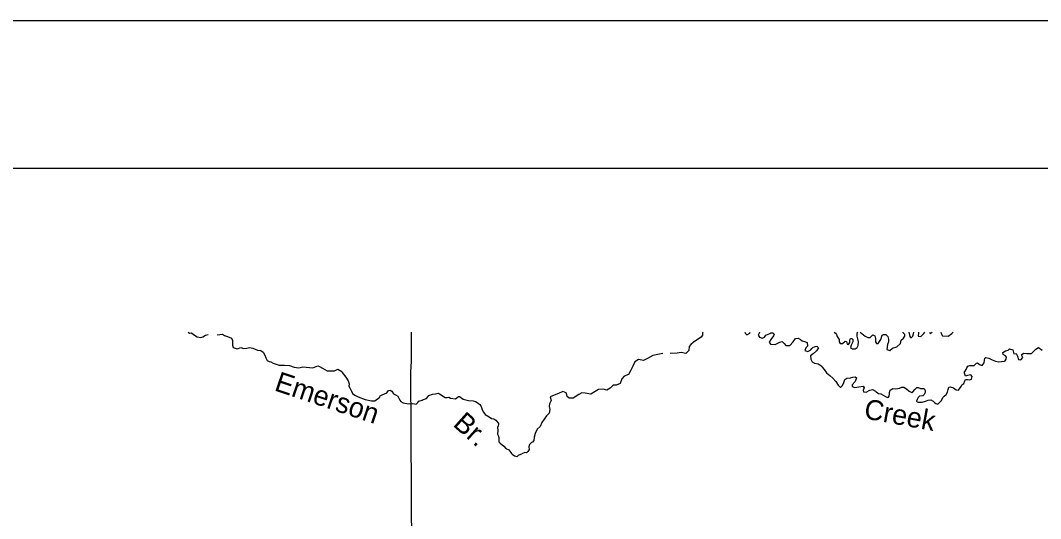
# Model space of a CAD drawing. Extents: x -492261 to -432772, y 1441225 to 1452922.
# Drawn here: x -459563.1 to -459293.9, y 1452515.2 to 1452646.6 of the extents above; entities that cross this region are included whole.
import ezdxf

# ---------------------------------------------------------------- set-up
doc = ezdxf.new("R2010")
doc.units = 0
for name, color, linetype in [('Default', 7, 'Continuous'), ('R_Border', 7, 'Continuous'), ('R_No Plot', 7, 'Continuous')]:
    doc.layers.add(name, color=color, linetype=linetype)

msp = doc.modelspace()

# ---------------------------------------------------------------- linework, layer by layer
at = {"layer": 'Default'}
for points in [[(-459518.78, 1452564.34), (-459518.45, 1452564.12), (-459517.9, 1452564.16), (-459517.4, 1452563.78), (-459516.45, 1452563.09), (-459515.5, 1452562.97), (-459514.93, 1452563.14), (-459514.23, 1452563.58), (-459513.49, 1452563.74)], [(-459511.17, 1452563.64), (-459509.74, 1452563.8), (-459509.24, 1452563.51), (-459508.43, 1452563.18), (-459507.41, 1452562.74), (-459507.1, 1452562.17), (-459507.12, 1452560.89), (-459506.93, 1452560.32), (-459505.92, 1452559.94), (-459504.93, 1452560.27), (-459504.18, 1452560.09), (-459503.33, 1452560.12), (-459502.59, 1452560.35), (-459501.78, 1452560.13), (-459500.5, 1452559.64), (-459499.62, 1452559.49), (-459499, 1452559.05), (-459498.58, 1452558.28), (-459498.29, 1452557.59), (-459497.94, 1452556.85), (-459497.41, 1452556.61), (-459496.99, 1452556.53), (-459496.4, 1452556.17), (-459494.8, 1452555.69), (-459493.36, 1452555.68), (-459492.1, 1452555.58), (-459490.81, 1452555.09), (-459489.63, 1452554.93), (-459488.54, 1452555.21), (-459487.65, 1452555.11), (-459485.93, 1452554.95), (-459484.59, 1452555.44), (-459484.14, 1452555.32), (-459483.37, 1452554.86), (-459482.16, 1452554.17), (-459480.17, 1452554.16), (-459479.34, 1452554.59), (-459478.27, 1452553.98), (-459478.14, 1452553.68), (-459477.22, 1452552.48), (-459476.55, 1452551.56), (-459476.37, 1452550.76), (-459476.45, 1452550.11), (-459476.07, 1452549.53), (-459475.75, 1452548.83), (-459475.44, 1452548.21), (-459474.79, 1452547.7), (-459473.91, 1452547.29), (-459472.11, 1452546.56), (-459470.47, 1452546.21), (-459469.56, 1452546.28), (-459468.26, 1452547.2), (-459468.12, 1452547.57), (-459467.6, 1452547.85), (-459466.36, 1452548.39), (-459465.96, 1452548.94), (-459465.54, 1452549.07), (-459465.1, 1452548.8), (-459464.6, 1452548.08), (-459464.06, 1452547.8), (-459463.49, 1452547.47), (-459462.97, 1452546.4)], [(-459458.97, 1452182.95), (-459458.72, 1452223.82), (-459458.96, 1452227.22), (-459459.32, 1452292.75), (-459459.97, 1452355.7), (-459459.94, 1452358.73), (-459460.05, 1452422.59), (-459460.04, 1452425.55), (-459459.65, 1452486.97), (-459459.67, 1452490.05), (-459460.02, 1452553.88), (-459459.91, 1452556.59), (-459459.92, 1452564.34)], [(-459383.03, 1452564.34), (-459383.06, 1452564.19), (-459383.11, 1452563.57), (-459383.48, 1452563.01), (-459384.93, 1452562.06), (-459385.59, 1452561.6), (-459386.17, 1452561.08), (-459386.62, 1452560.59), (-459386.67, 1452559.56), (-459387.45, 1452558.74), (-459388.74, 1452558.96), (-459389.76, 1452558.81), (-459391.66, 1452558.77)], [(-459371.89, 1452564.34), (-459371.81, 1452564.12), (-459371.36, 1452563.66), (-459370.61, 1452564.13), (-459370.49, 1452564.34)], [(-459368.03, 1452564.34), (-459368.09, 1452564.24), (-459368.37, 1452563.58), (-459368.05, 1452563.06), (-459367.32, 1452562.73), (-459366.73, 1452563.07), (-459366.36, 1452563.55), (-459365.79, 1452563.83), (-459365.36, 1452563.99), (-459365.04, 1452564.17), (-459364.53, 1452564.19), (-459364.22, 1452563.8), (-459364.4, 1452563.39), (-459365.03, 1452562.44), (-459365.49, 1452561.71), (-459365.13, 1452561.16), (-459363.95, 1452561.06), (-459362.71, 1452561.75), (-459362.11, 1452561.9), (-459361.59, 1452561.37), (-459361.1, 1452560.85), (-459360.05, 1452560.82), (-459359.18, 1452561.82), (-459358.54, 1452562.71), (-459357.82, 1452562.81), (-459357.26, 1452562.4), (-459356.84, 1452562.06), (-459356.17, 1452561.92), (-459355.52, 1452561.64), (-459355.38, 1452560.65), (-459355.8, 1452560.19), (-459356.08, 1452559.52), (-459355.3, 1452559.24), (-459354.49, 1452559.69), (-459354.21, 1452560.04), (-459353.86, 1452560.38), (-459352.94, 1452560.67), (-459352.52, 1452560.19), (-459352.99, 1452559.46), (-459353.93, 1452558.68), (-459354.6, 1452558.1), (-459354.54, 1452557.22), (-459354.19, 1452556.57), (-459353.5, 1452556.2), (-459352.6, 1452556.04), (-459352.14, 1452555.78), (-459351.62, 1452555.42), (-459351.48, 1452555.11), (-459350.99, 1452554.49), (-459350.4, 1452553.67), (-459349.5, 1452552.96), (-459348.72, 1452552.24), (-459347.93, 1452551.32), (-459347.31, 1452550.35), (-459346.64, 1452549.74), (-459346.14, 1452550.3), (-459345.79, 1452551.05), (-459345.58, 1452551.83), (-459345.02, 1452552.23), (-459344.03, 1452552.29), (-459343.43, 1452552.52), (-459342.79, 1452552.58), (-459342.45, 1452552.29), (-459342.83, 1452551.36), (-459343.58, 1452550.48), (-459343.64, 1452550.06), (-459342.9, 1452549.75), (-459341.88, 1452549.93), (-459340.69, 1452550.08), (-459340.44, 1452549.7), (-459340.69, 1452549.03), (-459340.62, 1452548.61), (-459339.93, 1452548.52), (-459338.98, 1452549.07), (-459338.2, 1452549.24), (-459337.44, 1452548.8), (-459337.26, 1452548.63), (-459336.69, 1452548.2), (-459336.02, 1452548.13), (-459334.84, 1452547.37), (-459334.27, 1452547.1), (-459334.05, 1452547.18), (-459333.82, 1452547.48), (-459333.74, 1452548.09), (-459333.73, 1452548.48), (-459333.6, 1452549.05), (-459332.85, 1452549.5), (-459332.16, 1452549.44), (-459331.55, 1452549.46), (-459331.15, 1452549.6), (-459330.53, 1452549.81), (-459329.96, 1452549.81), (-459329.26, 1452549.43), (-459328.56, 1452548.78), (-459327.85, 1452548.43), (-459327.58, 1452548.62), (-459327.04, 1452549.27)], [(-459348.37, 1452564.34), (-459348.04, 1452564.13), (-459347.78, 1452563.77), (-459347.53, 1452563.22), (-459347.06, 1452562.44), (-459347.07, 1452562.24), (-459347.04, 1452561.84), (-459346.8, 1452561.36), (-459346.18, 1452561.38), (-459345.49, 1452561.99), (-459345.09, 1452561.93), (-459344.95, 1452561.17), (-459344.54, 1452561.14), (-459344.25, 1452561.65), (-459344.26, 1452562.34), (-459344.03, 1452562.66), (-459343.66, 1452562.67), (-459343.39, 1452562.41), (-459343.43, 1452561.83), (-459343.84, 1452560.93), (-459344, 1452560.31), (-459343.49, 1452560), (-459342.85, 1452559.98), (-459342.28, 1452560.31), (-459341.98, 1452560.87), (-459341.93, 1452561.81), (-459342.09, 1452562.59), (-459342.25, 1452563.27), (-459342.29, 1452564.17), (-459342.15, 1452564.34)], [(-459341.46, 1452564.34), (-459341.03, 1452563.98), (-459340.17, 1452563.26), (-459339.44, 1452562.94), (-459338.82, 1452562.95), (-459338.11, 1452563.61), (-459337.62, 1452563.38), (-459337.49, 1452562.68), (-459337.45, 1452561.84), (-459337.21, 1452561.34), (-459336.72, 1452561.39), (-459336.05, 1452562.42), (-459335.71, 1452563.55), (-459335.37, 1452563.76), (-459334.68, 1452563.71), (-459334.19, 1452563.17), (-459333.99, 1452562.49), (-459334, 1452561.84), (-459334.24, 1452561.12), (-459334.48, 1452559.82), (-459333.64, 1452559.51), (-459332.97, 1452560.12), (-459331.85, 1452560.46), (-459330.89, 1452561.36), (-459330.67, 1452562.28), (-459330.09, 1452562.81), (-459329.68, 1452563.29), (-459329.71, 1452563.76), (-459330.11, 1452564.2), (-459330.19, 1452564.34)], [(-459328.65, 1452564.34), (-459328.37, 1452563.24), (-459328.17, 1452562.97), (-459327.92, 1452562.98), (-459327.57, 1452563.33), (-459327.41, 1452563.89), (-459327.31, 1452564.34)], [(-459326.07, 1452564.34), (-459326.07, 1452564.15), (-459326.16, 1452563.29), (-459325.47, 1452563.22), (-459324.7, 1452563.98), (-459324.42, 1452564.34)], [(-459323.21, 1452564.34), (-459323.04, 1452563.96), (-459322.5, 1452564.34)], [(-459320.22, 1452564.34), (-459320.12, 1452564), (-459319.75, 1452563.36), (-459318.31, 1452563.32), (-459317.33, 1452564.01), (-459316.94, 1452564.34)], [(-459327.04, 1452549.27), (-459326.52, 1452549.75), (-459326.18, 1452549.73), (-459325.56, 1452549.46), (-459325.16, 1452549.5), (-459324.6, 1452549.49), (-459324.34, 1452548.94), (-459324.35, 1452548.44), (-459324.57, 1452547.87), (-459325, 1452547.55), (-459325.85, 1452547.45), (-459326.21, 1452547.14), (-459326.49, 1452546.58), (-459326.62, 1452546.14), (-459326.47, 1452545.95), (-459326.13, 1452545.89), (-459325.84, 1452545.9), (-459325.26, 1452545.89), (-459325.12, 1452545.91), (-459324.27, 1452546.16), (-459324.01, 1452546.25), (-459323.52, 1452546.43), (-459322.88, 1452546.49), (-459322.22, 1452546.17), (-459321.92, 1452545.82), (-459321.57, 1452545.5), (-459321.02, 1452545.4), (-459320.05, 1452546.37), (-459319.69, 1452547.1), (-459319.32, 1452547.5), (-459318.77, 1452547.87), (-459318.42, 1452548.56), (-459318.29, 1452549.25), (-459318.14, 1452549.82), (-459317.73, 1452549.97), (-459316.83, 1452549.71), (-459316.16, 1452549.12), (-459315.52, 1452549.06), (-459314.88, 1452550.04), (-459314.69, 1452550.46), (-459314.17, 1452550.82), (-459313.89, 1452551.56), (-459313.71, 1452551.89), (-459313.21, 1452551.87), (-459312.67, 1452551.76), (-459312.1, 1452551.93), (-459311.9, 1452552.62), (-459312.25, 1452553.07), (-459313.16, 1452552.96), (-459313.68, 1452552.74), (-459314, 1452553.5), (-459313.99, 1452553.98), (-459313.75, 1452554.11), (-459313.53, 1452554.53), (-459313.39, 1452554.98), (-459313.04, 1452555.42), (-459312.55, 1452555.55), (-459311.45, 1452555.57), (-459310.79, 1452556.2), (-459310.53, 1452556.26), (-459309.85, 1452555.76), (-459309.34, 1452555.53), (-459308.8, 1452556.24), (-459308.67, 1452556.98), (-459308.6, 1452557.46), (-459308.31, 1452557.71), (-459307.52, 1452557.51), (-459306.68, 1452557.02), (-459305.77, 1452556.7), (-459304.99, 1452556.56), (-459303.39, 1452556.72), (-459303.23, 1452556.79), (-459302.96, 1452557.19), (-459302.84, 1452557.72), (-459303.12, 1452558.08), (-459303.77, 1452558.48), (-459303.86, 1452558.96), (-459303.13, 1452559.47), (-459302.4, 1452559.61), (-459302.07, 1452560), (-459301.2, 1452559.66), (-459300.92, 1452558.68), (-459300.29, 1452558.75), (-459300.02, 1452557.99), (-459299.72, 1452557.18), (-459299.08, 1452557.07), (-459298.6, 1452557.67), (-459298.91, 1452558.38), (-459298.41, 1452558.78), (-459297.52, 1452558.74), (-459296.28, 1452558.72), (-459295.14, 1452559.89), (-459294.47, 1452560.28), (-459293.46, 1452559.6)], [(-459393.54, 1452558.72), (-459396.21, 1452558.17), (-459397.62, 1452557.4), (-459398.66, 1452556.88), (-459399.99, 1452557.12), (-459400.91, 1452556.56), (-459401.44, 1452555.38), (-459402.11, 1452554.16)], [(-459402.11, 1452554.16), (-459402.61, 1452553.18), (-459403.79, 1452552.73), (-459404.39, 1452552.08), (-459404.79, 1452550.84), (-459405.84, 1452550.4), (-459406.71, 1452550.4), (-459407.44, 1452549.59), (-459408.32, 1452549.02), (-459409.3, 1452549.32), (-459410.56, 1452549.21), (-459411.41, 1452548.66), (-459412.6, 1452548.01), (-459414.08, 1452548.24), (-459414.97, 1452548.39), (-459415.76, 1452547.87), (-459417.25, 1452546.95), (-459418.25, 1452546.98), (-459418.83, 1452547.41), (-459418.92, 1452547.84), (-459419.07, 1452548.36), (-459419.91, 1452548.73), (-459421.05, 1452548.2), (-459422.25, 1452547.78), (-459423.26, 1452547.3), (-459423.07, 1452546.33), (-459423.49, 1452545.49), (-459423.51, 1452544.75), (-459423.41, 1452543.99), (-459423.51, 1452543.02), (-459424.23, 1452542.26), (-459424.83, 1452541.44), (-459425.47, 1452540.5), (-459425.93, 1452539.46), (-459426.74, 1452538.73), (-459427.22, 1452537.6), (-459427.53, 1452536.64), (-459427.59, 1452535.76), (-459427.91, 1452535.3), (-459428.24, 1452535.26), (-459428.71, 1452534.71), (-459428.91, 1452534.12), (-459428.84, 1452533.41), (-459429.14, 1452532.87), (-459429.57, 1452532.56), (-459429.96, 1452532.58), (-459430.77, 1452532.24)], [(-459462.97, 1452546.4), (-459462.69, 1452546.06), (-459462.11, 1452545.73), (-459460.67, 1452545.42), (-459459.57, 1452545.56), (-459458.64, 1452545.39), (-459458.17, 1452545.8), (-459457.92, 1452546.18), (-459457.08, 1452546.39), (-459456.76, 1452546.57), (-459456.44, 1452546.67), (-459455.96, 1452546.87), (-459455.57, 1452547.26), (-459455.28, 1452547.67), (-459454.34, 1452547.96), (-459453.55, 1452548.09), (-459452.85, 1452548.28), (-459452.46, 1452548.12), (-459451.01, 1452547.14), (-459450.46, 1452547.09), (-459450.06, 1452547.25), (-459449.62, 1452546.95), (-459448.24, 1452546.74), (-459447.49, 1452547.42), (-459447.25, 1452547.35), (-459446.28, 1452546.69), (-459444.87, 1452546.34), (-459443.62, 1452546.27), (-459443, 1452546.09), (-459442.25, 1452545.6), (-459441.87, 1452545.26), (-459441.58, 1452544.93), (-459441.41, 1452544.44), (-459441.2, 1452543.89), (-459440.9, 1452543.29), (-459440.41, 1452542.65), (-459439.4, 1452542.03), (-459438.78, 1452541.58), (-459438.15, 1452541.49), (-459437.6, 1452541.18), (-459437.17, 1452540.61), (-459436.95, 1452540.24), (-459436.95, 1452540.01), (-459436.98, 1452539.65), (-459437.23, 1452539.17), (-459437.12, 1452538.38), (-459437.21, 1452537.45), (-459437.05, 1452537.09), (-459436.82, 1452536.55), (-459436.81, 1452535.92), (-459436.84, 1452535.43), (-459436.51, 1452535.06), (-459435.51, 1452534.31), (-459435, 1452533.7), (-459434.17, 1452533.34), (-459433.69, 1452532.64), (-459433.52, 1452532.33), (-459433.28, 1452532.21), (-459432.71, 1452531.73), (-459432, 1452531.54), (-459431.65, 1452531.88), (-459431.46, 1452532.02), (-459430.77, 1452532.24)]]:
    msp.add_lwpolyline(points, dxfattribs=at)
at = {"layer": 'R_Border'}
msp.add_line((-459957.64, 1452607.65), (-456795.84, 1452607.65), dxfattribs=at)
at = {"layer": 'R_No Plot'}
msp.add_line((-460081.65, 1452646.6), (-456748.31, 1452646.6), dxfattribs=at)
for points in [[(-460081.71, 1452646.6), (-456748.31, 1452646.6), (-456748.31, 1450513.22), (-460081.71, 1450513.22)], [(-457618.44, 1452607.65), (-457618.44, 1452508.85), (-457261.12, 1452508.85), (-457261.12, 1452479.65), (-457029.12, 1452479.65), (-457029.12, 1452236.32), (-456795.84, 1452236.32), (-456795.84, 1450553.05), (-459957.64, 1450553.05), (-459957.64, 1452607.65)]]:
    msp.add_lwpolyline(points, close=True, dxfattribs=at)

# ---------------------------------------------------------------- texts
at = {"layer": 'Default'}
for s, rotation, p in [('Emerson', 341.4723, (-459496.32, 1452549.06)), ('Creek', 349.5994, (-459340.72, 1452541.66)), ('Br.', 318.2557, (-459449.19, 1452539.8))]:
    msp.add_text(s, height=5.28, rotation=rotation, dxfattribs=at).set_placement(p)

doc.saveas('drawing.dxf')
